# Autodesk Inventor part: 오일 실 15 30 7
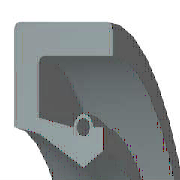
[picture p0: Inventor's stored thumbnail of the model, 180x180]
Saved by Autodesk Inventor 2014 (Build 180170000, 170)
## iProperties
IsCustomPart: 1
Created: 2012-02
Part Number: 오일 실 15 30 7
Material: 고무
Description: 오일-실
Document SubType Name: Modeling
Standard: KS B 2804
Designer: mduedu
Standards Organization: KS
Language: ko-KR
Size Designation: S - 15 30 7
Categories: <MemberInstance><Categories><Category DisplayName="샤프트 부품" InternalName="7f7aeb1f-a693-4053-b835-cee3144e0d98" Mnemonic="SHFT"><Category DisplayName="실링" Intern
Density: 0.93 g/cm^3
Appearance: 고무 - 검은색 - 버전 1.1
Author: mduedu
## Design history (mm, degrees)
revolve "본체" stored, may be unused: angle "d17" = 90 deg
revolve "스프링1" stored, may be unused: angle "d18" = 90 deg
body "Solid1"
sketch "스케치1"
  geometry: L1 (0, 15)-(7, 15); L2 (7, 15)-(7, 13.75); L3 (7, 13.75)-(1.75, 13.75); L4 (0, 15)-(0, 9.6); L5 (0, 9.6)-(1.75, 9.25); L6 (1.75, 9.25)-(4.9, 7.5); L7 (4.9, 7.5)-(0, 7.5); L8 (6.3, 8.375)-(6.3, 9.6); L9 (0, 0)-(9.586, 0) reference; L10 (4.9, 7.5)-(6.3, 8.375); L11 (0, 18)-(0, -3) reference; L12 (-1.917, 0)-(11.503, 0) reference; L13 (4.2, 9.6)-(1.75, 10.09); L14 (1.75, 10.09)-(1.75, 13.75); L15 (6.3, 9.6)-(5.6, 9.6); C1 r 0.455 at (4.9, 9.6); A1 r 0.7 centre (4.9, 9.6) between (5.6, 9.6) and (4.2, 9.6)
  constraints: 26 end point, 5 horizontal alignment, 4 perpendicular, 2 centre point, 2 collinear, 2 horizontal, 2 parallel, 2 point on circle, 2 point on line, 2 vertical alignment, 1 coincident
  dimensions: "d0" = 30 diameter of L1 L9 (= SD2); "d1" = 16.75 diameter of L8.start L9 (= ABDM); "d2" = 1.25 distance of L1.end L2.end (computed from SD); "d3" = 0.91 diameter of C1 (= SPDI); "d4" = 1.4 diameter of A1 (= SPDA); "d5" = 15 diameter of L6.end L9 (= NND); "d6" = 18.5 diameter of L5.end L9 (= TKDM); "d7" = 19.2 diameter of L4.end L9 (= HLDM); "d8" = 4.9 distance from line of C1.centre L4 (= SPDST); "d9" = 6.3 distance between parallel lines of L8 L4 (= SDI); "d10" = 7 distance between parallel lines of L2 L4 (= SWDT); "d12" = 1.75 distance between parallel lines of L14 L4 (= SD)
fillet "모깎기1" dims "d11" = 0.3 (= RR)
other parameters: "SD2" = 30 [user parameter; used in 1 equation term], "SWDT" = 7 [user parameter; used in 1 equation term], "RR" = 0.3 [user parameter; used in 1 equation term], "SD" = 1.75 [user parameter; used in 2 equation terms], "NND" = 15 [user parameter; used in 1 equation term], "SPDA" = 1.4 [user parameter; used in 1 equation term], "SPDI" = 0.91 [user parameter; used in 1 equation term], "TKDM" = 18.5 [user parameter; used in 1 equation term], "HLDM" = 19.2 [user parameter; used in 1 equation term], "ABDM" = 16.75 [user parameter; used in 1 equation term], "SDI" = 6.3 [user parameter; used in 1 equation term], "SPDST" = 4.9 [user parameter; used in 1 equation term], "d13" = 0, "d14" = 0, "d15" = 0, "LAB" = 0.35 [user parameter]
